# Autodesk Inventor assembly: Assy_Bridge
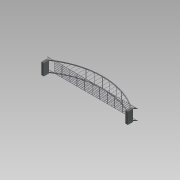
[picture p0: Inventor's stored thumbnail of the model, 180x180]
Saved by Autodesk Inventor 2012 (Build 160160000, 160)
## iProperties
Created: 2016-07
Part Number: Assy_Bridge
Document SubType Name: Assembly
Designer: talhah
_SolveAssemblyDoc: Frame Generator Solve Assembly
_Version: 15.0.0
Author: talhah
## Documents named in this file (4)
- D:\My Proyek_3D\Project Drafter\Tower\Bridge\Assy_Bridge.iam
- D:\My Proyek_3D\Project Drafter\Tower\Bridge\Sketch_2.ipt
- D:\My Proyek_3D\Project Drafter\Tower\Bridge\Assy_Bridge\Frame\Frame0001.iam
- D:\My Proyek_3D\Project Drafter\Tower\Bridge\Pondasi.ipt
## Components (4 placed, 3 different names)
1. Sketch_2:1
2. Frame0001:1 [sub-assembly] — Mate:1, Mate:2, Flush:1, Flush:2, Mate:3, Flush:3, Flush:4
3. Pondasi:1 — Mate:1, Mate:2, Flush:1, Flush:2
4. Pondasi:2 — Mate:3, Flush:3, Flush:4
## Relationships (7: Flush 4, Mate 3)
- Mate:1: Frame0001:1 ↔ Pondasi:1
- Mate:2: Frame0001:1 ↔ Pondasi:1
- Flush:1: Frame0001:1 ↔ Pondasi:1
- Flush:2: Frame0001:1 ↔ Pondasi:1
- Mate:3: Frame0001:1 ↔ Pondasi:2
- Flush:3: Frame0001:1 ↔ Pondasi:2
- Flush:4: Frame0001:1 ↔ Pondasi:2
